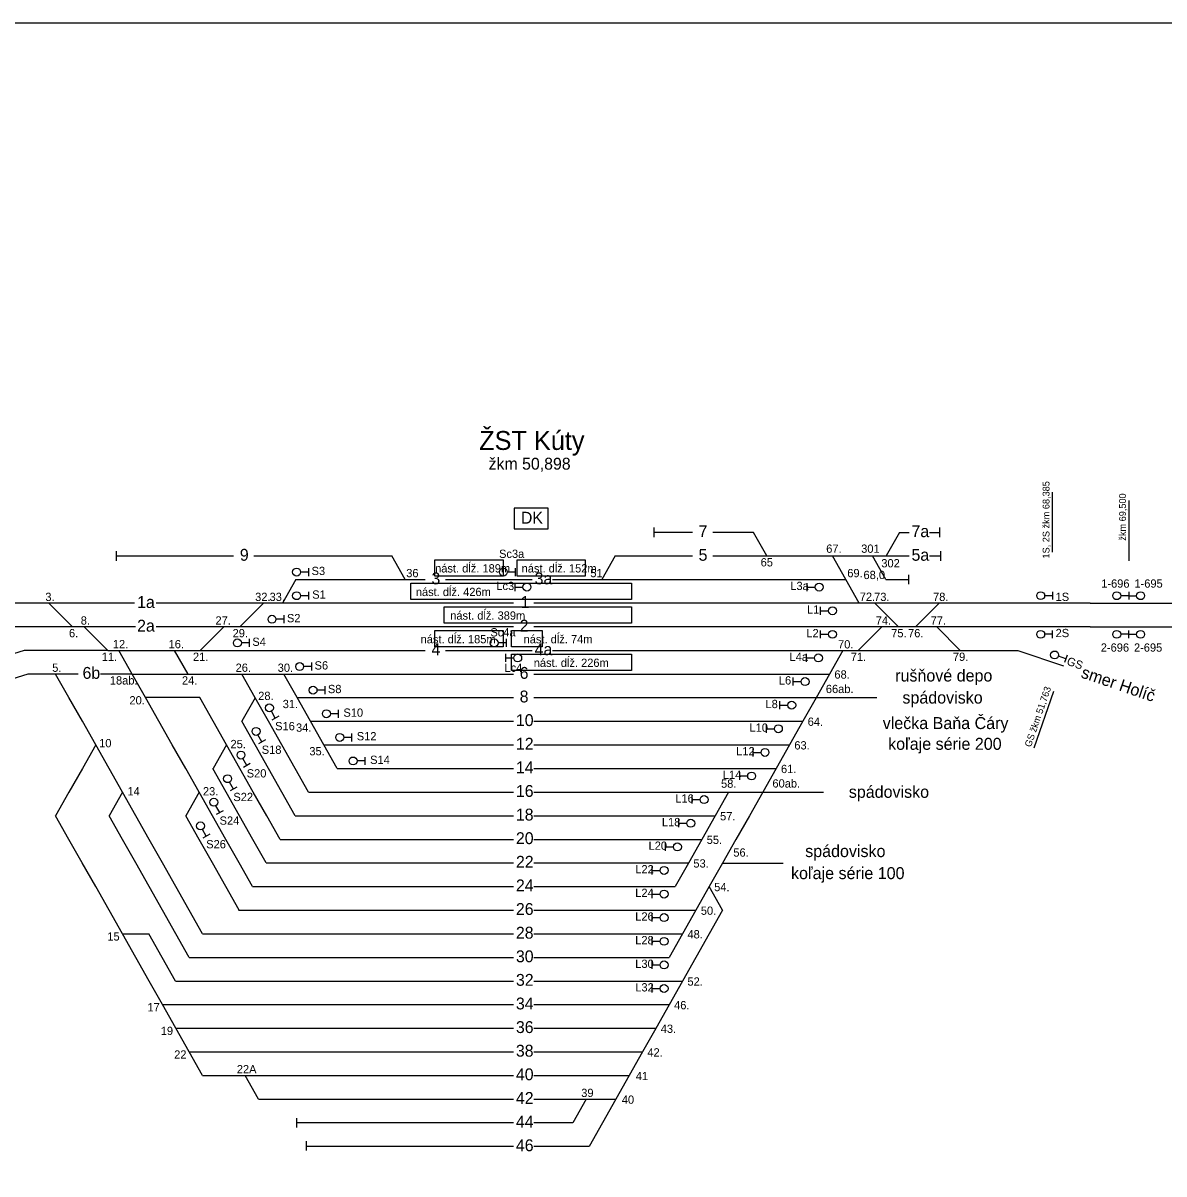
# Model space of a CAD drawing. Extents: x -119 to 851, y -238 to 59.
# Drawn here: x 501.6 to 598.1, y -38.4 to 59 of the extents above; entities that cross this region are included whole.
import ezdxf

# ---------------------------------------------------------------- set-up
doc = ezdxf.new("R2010")
doc.units = 0
for name, color, linetype in [('budova', 7, 'Continuous'), ('Level 2', 7, 'Continuous'), ('nastupistia', 7, 'Continuous'), ('netlač', 7, 'Continuous'), ('popisky navestidla', 7, 'Continuous'), ('popisky stanic a zastavok', 7, 'Continuous'), ('PU_navestidla', 7, 'Continuous'), ('PU_oznacenie navestidiel', 7, 'Continuous'), ('PU_stan_kolaje', 7, 'Continuous'), ('PU_vlecky', 7, 'Continuous'), ('schema_km1-0', 7, 'Continuous')]:
    doc.layers.add(name, color=color, linetype=linetype)

msp = doc.modelspace()

# ---------------------------------------------------------------- linework, layer by layer
at = {"layer": 'budova'}
msp.add_lwpolyline([(546.002, 17.928), (543.135, 17.928), (543.135, 16.18), (546.002, 16.18)], close=True, dxfattribs=at)
at = {"layer": 'Level 2'}
for p, q in [((554.952, 16.285), (554.952, 15.485)), ((579.115, 16.285), (579.115, 15.485)), ((509.446, 14.286), (509.446, 13.487)), ((579.194, 14.286), (579.194, 13.486)), ((576.487, 12.287), (576.487, 11.488)), ((511.009, 9.889), (496.537, 9.889)), ((523.736, 9.889), (512.835, 9.889)), ((543.056, 9.889), (523.736, 9.889)), ((553.177, 9.889), (544.779, 9.889)), ((567.83, 9.889), (553.177, 9.889)), ((591.856, 9.889), (567.83, 9.889)), ((511.071, 7.89), (496.537, 7.89)), ((543.056, 7.89), (512.817, 7.89)), ((553.177, 7.89), (544.779, 7.89)), ((566.63, 7.89), (553.177, 7.89)), ((582.828, 7.89), (566.63, 7.89)), ((591.856, 7.89), (582.828, 7.89)), ((524.714, -33.689), (524.714, -34.489)), ((525.51, -35.629), (525.51, -36.428))]:
    msp.add_line(p, q, dxfattribs=at)
at = {"layer": 'nastupistia'}
for points in [[(536.416, 13.571), (542.191, 13.571), (542.191, 12.186), (536.416, 12.186)], [(543.364, 13.571), (549.139, 13.571), (549.139, 12.186), (543.364, 12.186)], [(534.378, 11.576), (553.061, 11.576), (553.061, 10.191), (534.378, 10.191)], [(537.188, 9.577), (553.061, 9.577), (553.061, 8.192), (537.188, 8.192)], [(536.416, 7.576), (542.191, 7.576), (542.191, 6.191), (536.416, 6.191)], [(542.901, 7.576), (545.495, 7.576), (545.495, 6.191), (542.901, 6.191)], [(542.901, 5.578), (553.061, 5.578), (553.061, 4.193), (542.901, 4.193)]]:
    msp.add_lwpolyline(points, close=True, dxfattribs=at)
at = {"layer": 'netlač'}
for p, q in [((558.196, 15.885), (554.952, 15.885)), ((563.377, 15.885), (559.919, 15.885)), ((575.729, 15.885), (576.53, 15.885)), ((578.254, 15.885), (579.115, 15.885)), ((509.446, 13.887), (519.382, 13.886)), ((521.105, 13.886), (532.767, 13.886)), ((551.667, 13.887), (558.196, 13.886)), ((559.919, 13.886), (570.062, 13.886)), ((570.062, 13.886), (576.53, 13.886)), ((578.254, 13.886), (579.194, 13.886)), ((524.649, 11.888), (535.593, 11.888)), ((537.316, 11.888), (544.643, 11.888)), ((546.366, 11.888), (571.192, 11.888)), ((574.579, 11.888), (576.487, 11.888)), ((591.856, 9.889), (629.005, 9.889)), ((591.856, 7.89), (629.005, 7.89)), ((501.658, 5.891), (490.127, 2.209)), ((508.74, 5.891), (501.658, 5.891)), ((508.74, 5.891), (535.593, 5.891)), ((537.316, 5.891), (544.643, 5.891)), ((546.366, 5.891), (580.871, 5.891)), ((580.871, 5.891), (585.745, 5.891)), ((585.745, 5.891), (589.598, 4.576)), ((501.97, 3.892), (500.087, 3.291)), ((504.324, 3.892), (501.97, 3.892)), ((506.243, 3.892), (504.324, 3.892)), ((510.809, 3.892), (508.115, 3.892)), ((510.809, 3.892), (543.056, 3.892)), ((544.779, 3.892), (569.802, 3.892)), ((524.755, 1.894), (543.056, 1.894)), ((544.779, 1.894), (568.672, 1.894)), ((568.672, 1.894), (573.804, 1.894)), ((525.885, -0.105), (543.056, -0.105)), ((544.779, -0.105), (567.542, -0.105)), ((527.015, -2.103), (543.056, -2.103)), ((544.779, -2.103), (566.412, -2.103)), ((528.144, -4.102), (543.056, -4.102)), ((544.779, -4.102), (565.282, -4.102)), ((525.715, -6.101), (543.056, -6.101)), ((544.779, -6.101), (564.152, -6.101)), ((564.15, -6.103), (569.282, -6.103)), ((524.585, -8.1), (543.056, -8.1)), ((544.779, -8.1), (560.131, -8.1)), ((523.311, -10.097), (543.056, -10.097)), ((544.779, -10.097), (559.002, -10.097)), ((522.144, -12.094), (543.056, -12.094)), ((544.779, -12.094), (557.873, -12.094)), ((560.76, -12.1), (565.892, -12.1)), ((520.978, -14.094), (543.056, -14.094)), ((544.779, -14.094), (556.742, -14.094)), ((519.811, -16.091), (543.056, -16.091)), ((544.779, -16.091), (558.503, -16.091)), ((509.973, -18.093), (512.217, -18.093)), ((516.757, -18.097), (543.056, -18.097)), ((544.779, -18.097), (557.369, -18.097)), ((515.627, -20.096), (543.056, -20.096)), ((544.779, -20.096), (556.239, -20.096)), ((514.477, -22.09), (543.056, -22.09)), ((544.779, -22.09), (557.372, -22.09)), ((513.363, -24.088), (543.056, -24.088)), ((544.779, -24.088), (556.242, -24.088)), ((514.493, -26.087), (543.056, -26.087)), ((544.779, -26.087), (555.112, -26.087)), ((515.623, -28.085), (543.056, -28.085)), ((544.779, -28.085), (553.982, -28.085)), ((516.753, -30.084), (543.056, -30.084)), ((544.779, -30.084), (552.852, -30.084)), ((521.487, -32.082), (543.056, -32.082)), ((544.779, -32.082), (551.722, -32.082)), ((543.056, -34.089), (524.714, -34.089)), ((548.081, -34.089), (544.779, -34.089)), ((543.056, -36.088), (525.51, -36.088)), ((549.457, -36.088), (544.779, -36.088))]:
    msp.add_line(p, q, dxfattribs=at)
at = {"layer": 'popisky navestidla'}
for p, q in [((588.677, 14.202), (588.677, 19.293)), ((595.147, 13.488), (595.147, 18.579)), ((588.742, 2.424), (587.098, -2.394))]:
    msp.add_line(p, q, dxfattribs=at)
msp.add_lwpolyline([(-118.951, -238.008), (851.049, -238.008), (851.049, 58.992), (-118.951, 58.992)], close=True, dxfattribs=at)
at = {"layer": 'PU_navestidla'}
for p, q in [((525.724, 12.86), (525.724, 12.188)), ((543.213, 12.86), (543.213, 12.188)), ((525.724, 12.522), (525.052, 12.522)), ((543.213, 12.522), (542.541, 12.522)), ((525.724, 10.861), (525.724, 10.189)), ((543.192, 10.916), (543.192, 11.588)), ((543.192, 11.253), (543.864, 11.253)), ((567.919, 10.916), (567.919, 11.588)), ((567.919, 11.253), (568.591, 11.253)), ((588.677, 10.862), (588.677, 10.19)), ((595.114, 10.86), (595.114, 10.188)), ((595.114, 10.86), (595.114, 10.188)), ((525.724, 10.523), (525.052, 10.523)), ((588.677, 10.525), (588.005, 10.525)), ((595.114, 10.522), (594.442, 10.522)), ((595.114, 10.522), (595.786, 10.522)), ((523.639, 8.862), (523.639, 8.19)), ((569.049, 8.917), (569.049, 9.589)), ((569.049, 9.254), (569.721, 9.254)), ((523.639, 8.524), (522.967, 8.524)), ((520.712, 6.863), (520.712, 6.191)), ((542.437, 6.863), (542.437, 6.191)), ((569.049, 6.918), (569.049, 7.59)), ((569.049, 7.255), (569.721, 7.255)), ((588.677, 7.255), (588.005, 7.255)), ((588.677, 6.918), (588.677, 7.59)), ((595.114, 7.254), (594.442, 7.254)), ((595.114, 6.917), (595.114, 7.589)), ((595.114, 6.917), (595.114, 7.589)), ((595.114, 7.254), (595.786, 7.254)), ((520.712, 6.525), (520.04, 6.525)), ((542.437, 6.526), (541.765, 6.526)), ((542.411, 4.92), (542.411, 5.592)), ((542.411, 5.257), (543.083, 5.257)), ((567.856, 4.92), (567.856, 5.592)), ((567.856, 5.257), (568.528, 5.257)), ((589.804, 5.178), (589.168, 5.395)), ((589.913, 5.497), (589.696, 4.861)), ((525.98, 4.526), (525.308, 4.526)), ((525.98, 4.864), (525.98, 4.192)), ((566.726, 2.921), (566.726, 3.593)), ((566.726, 3.258), (567.398, 3.258)), ((527.11, 2.528), (526.438, 2.528)), ((527.11, 2.865), (527.11, 2.193)), ((565.596, 0.923), (565.596, 1.595)), ((565.596, 1.26), (566.268, 1.26)), ((522.907, 0.155), (522.576, 0.74)), ((523.2, 0.321), (522.615, -0.01)), ((528.24, 0.529), (527.568, 0.529)), ((528.24, 0.867), (528.24, 0.195)), ((564.466, -1.076), (564.466, -0.404)), ((564.466, -0.738), (565.138, -0.738)), ((521.777, -1.844), (521.446, -1.259)), ((522.07, -1.678), (521.485, -2.009)), ((529.37, -1.469), (528.698, -1.469)), ((529.37, -1.132), (529.37, -1.804)), ((563.336, -3.074), (563.336, -2.402)), ((563.336, -2.737), (564.008, -2.737)), ((520.502, -3.842), (520.172, -3.257)), ((520.796, -3.676), (520.211, -4.006)), ((530.5, -3.467), (529.828, -3.467)), ((530.5, -3.13), (530.5, -3.802)), ((562.206, -5.073), (562.206, -4.401)), ((562.206, -4.735), (562.878, -4.735)), ((519.372, -5.841), (519.041, -5.256)), ((519.666, -5.675), (519.081, -6.005)), ((558.185, -7.072), (558.185, -6.4)), ((558.185, -6.734), (558.857, -6.734)), ((518.206, -7.839), (517.875, -7.254)), ((518.499, -7.673), (517.914, -8.004)), ((557.055, -9.071), (557.055, -8.399)), ((557.055, -8.733), (557.727, -8.733)), ((517.075, -9.838), (516.745, -9.253)), ((517.369, -9.672), (516.784, -10.003)), ((555.925, -11.07), (555.925, -10.398)), ((555.925, -10.732), (556.597, -10.732)), ((554.798, -13.062), (554.798, -12.39)), ((554.798, -12.725), (555.47, -12.725)), ((554.798, -15.062), (554.798, -14.39)), ((554.798, -14.725), (555.47, -14.725)), ((554.798, -17.059), (554.798, -16.387)), ((554.798, -16.722), (555.47, -16.722)), ((554.798, -19.066), (554.798, -18.394)), ((554.798, -18.728), (555.47, -18.728)), ((554.798, -21.065), (554.798, -20.393)), ((554.798, -20.727), (555.47, -20.727)), ((554.798, -23.058), (554.798, -22.386)), ((554.798, -22.721), (555.47, -22.721))]:
    msp.add_line(p, q, dxfattribs=at)
for centre in [(524.716, 12.524), (542.205, 12.524), (524.716, 10.525), (544.2, 11.252), (568.927, 11.252), (587.669, 10.526), (594.106, 10.524), (596.122, 10.524), (522.631, 8.526), (570.057, 9.253), (519.704, 6.527), (541.429, 6.527), (570.057, 7.254), (587.669, 7.254), (594.106, 7.253), (596.122, 7.253), (543.419, 5.256), (568.864, 5.256), (588.85, 5.505), (524.972, 4.528), (567.734, 3.257), (526.102, 2.529), (522.412, 1.033), (566.604, 1.259), (527.232, 0.531), (521.282, -0.966), (565.474, -0.74), (528.362, -1.468), (520.008, -2.964), (564.344, -2.738), (529.492, -3.466), (518.877, -4.963), (563.214, -4.737), (517.711, -6.961), (559.193, -6.736), (516.581, -8.96), (558.063, -8.735), (556.933, -10.734), (555.806, -12.726), (555.806, -14.726), (555.806, -16.723), (555.806, -18.73), (555.806, -20.729), (555.806, -22.722)]:
    msp.add_circle(centre, 0.336, dxfattribs=at)
at = {"layer": 'PU_stan_kolaje'}
for points in [[(564.507, 13.887), (563.377, 15.885)], [(575.729, 15.885), (574.598, 13.886)], [(533.897, 11.888), (532.767, 13.886)], [(551.667, 13.887), (550.537, 11.888)], [(571.192, 11.888), (570.062, 13.886)], [(574.579, 11.888), (573.45, 13.886)], [(524.649, 11.888), (523.518, 9.889)], [(572.322, 9.889), (571.192, 11.887)], [(505.743, 7.89), (503.744, 9.889)], [(519.905, 7.89), (521.904, 9.889)], [(575.649, 7.89), (573.65, 9.889)], [(577.076, 7.89), (579.075, 9.889)], [(508.74, 5.891), (506.741, 7.89)], [(516.549, 5.891), (518.548, 7.89)], [(572.23, 5.891), (574.229, 7.89)], [(580.871, 5.891), (578.872, 7.89)], [(510.809, 3.892), (509.679, 5.891)], [(515.525, 3.892), (514.395, 5.891)], [(570.932, 5.891), (569.802, 3.892)], [(505.454, 1.894), (504.324, 3.892)], [(511.938, 1.894), (510.809, 3.892)], [(521.196, 1.893), (520.066, 3.892)], [(524.755, 1.894), (523.625, 3.892)], [(569.802, 3.892), (568.671, 1.893)], [(506.584, -0.105), (505.454, 1.894)], [(513.068, -0.105), (511.938, 1.894)], [(516.531, 1.894), (511.938, 1.894)], [(517.661, -0.105), (516.531, 1.894)], [(521.196, 1.893), (520.065, -0.106)], [(522.325, -0.105), (521.196, 1.893)], [(525.885, -0.105), (524.755, 1.894)], [(568.671, 1.893), (567.541, -0.106)], [(507.714, -2.103), (506.584, -0.105)], [(514.198, -2.103), (513.068, -0.105)], [(518.791, -2.103), (517.661, -0.105)], [(521.195, -2.104), (520.065, -0.106)], [(523.455, -2.104), (522.325, -0.105)], [(527.015, -2.103), (525.885, -0.105)], [(567.541, -0.106), (566.411, -2.105)], [(507.714, -2.103), (506.584, -4.102)], [(508.844, -4.102), (507.714, -2.103)], [(515.328, -4.102), (514.198, -2.103)], [(518.791, -2.103), (517.661, -4.102)], [(519.921, -4.102), (518.791, -2.103)], [(522.325, -4.103), (521.195, -2.104)], [(524.585, -4.102), (523.455, -2.104)], [(528.144, -4.102), (527.015, -2.103)], [(566.411, -2.105), (565.281, -4.104)], [(506.584, -4.102), (505.454, -6.101)], [(509.974, -6.1), (508.844, -4.102)], [(516.458, -6.1), (515.328, -4.102)], [(518.755, -6.1), (517.625, -4.102)], [(521.051, -6.1), (519.921, -4.102)], [(523.455, -6.101), (522.325, -4.103)], [(525.715, -6.101), (524.585, -4.102)], [(565.281, -4.104), (564.15, -6.103)], [(505.454, -6.101), (504.323, -8.1)], [(509.974, -6.1), (508.844, -8.099)], [(511.104, -8.099), (509.974, -6.1)], [(516.458, -6.1), (515.328, -8.099)], [(517.588, -8.099), (516.458, -6.1)], [(519.885, -8.099), (518.755, -6.1)], [(522.181, -8.099), (521.051, -6.1)], [(524.585, -8.1), (523.455, -6.101)], [(561.26, -6.103), (560.13, -8.102)], [(564.15, -6.103), (563.02, -8.102)], [(505.453, -10.099), (504.323, -8.1)], [(509.974, -10.098), (508.844, -8.099)], [(512.234, -10.097), (511.104, -8.099)], [(516.458, -10.098), (515.328, -8.099)], [(518.718, -10.097), (517.588, -8.099)], [(521.015, -10.097), (519.885, -8.099)], [(523.311, -10.097), (522.181, -8.099)], [(560.13, -8.102), (558.999, -10.101)], [(563.02, -8.102), (561.89, -10.101)], [(506.583, -12.097), (505.453, -10.099)], [(511.104, -12.096), (509.974, -10.098)], [(513.364, -12.096), (512.234, -10.097)], [(517.588, -12.096), (516.458, -10.098)], [(519.848, -12.096), (518.718, -10.097)], [(522.145, -12.096), (521.015, -10.097)], [(558.999, -10.101), (557.869, -12.1)], [(561.89, -10.101), (560.76, -12.1)], [(507.713, -14.096), (506.583, -12.097)], [(512.234, -14.095), (511.104, -12.096)], [(514.494, -14.094), (513.364, -12.096)], [(518.718, -14.095), (517.588, -12.096)], [(520.978, -14.094), (519.848, -12.096)], [(557.869, -12.1), (556.739, -14.099)], [(560.76, -12.1), (559.629, -14.099)], [(508.843, -16.094), (507.713, -14.096)], [(513.364, -16.093), (512.234, -14.095)], [(515.624, -16.093), (514.494, -14.094)], [(519.848, -16.093), (518.718, -14.095)], [(559.629, -14.099), (558.499, -16.098)], [(560.759, -16.098), (559.629, -14.099)], [(509.973, -18.093), (508.843, -16.094)], [(514.494, -18.092), (513.364, -16.093)], [(516.754, -18.091), (515.624, -16.093)], [(558.499, -16.098), (557.369, -18.097)], [(560.759, -16.098), (559.629, -18.097)], [(511.103, -20.091), (509.973, -18.093)], [(513.347, -20.091), (512.217, -18.093)], [(515.624, -20.09), (514.494, -18.092)], [(557.369, -18.097), (556.239, -20.096)], [(559.629, -18.097), (558.499, -20.096)], [(512.233, -22.09), (511.103, -20.091)], [(514.477, -22.09), (513.347, -20.091)], [(558.499, -20.096), (557.369, -22.095)], [(513.363, -24.088), (512.233, -22.09)], [(557.369, -22.095), (556.238, -24.094)], [(514.493, -26.087), (513.363, -24.088)], [(556.238, -24.094), (555.108, -26.093)], [(515.623, -28.085), (514.493, -26.087)], [(555.108, -26.093), (553.978, -28.092)], [(516.753, -30.084), (515.623, -28.085)], [(553.978, -28.092), (552.848, -30.091)], [(521.487, -32.082), (520.357, -30.084)], [(552.848, -30.091), (551.717, -32.09)], [(549.211, -32.09), (548.081, -34.089)], [(551.717, -32.09), (550.587, -34.089)], [(550.587, -34.089), (549.457, -36.088)]]:
    msp.add_lwpolyline(points, dxfattribs=at)

# ---------------------------------------------------------------- texts
at = {"layer": 'budova'}
msp.add_text('DK', height=1.0044, dxfattribs=at).set_placement((543.69, 16.619))
at = {"layer": 'nastupistia'}
for s, p in [('nást. dĺž. 189m', (536.431, 12.489)), ('nást. dĺž. 152m', (543.75, 12.489)), ('nást. dĺž. 426m', (534.799, 10.493)), ('nást. dĺž. 389m', (537.711, 8.494)), ('nást. dĺž. 185m', (535.204, 6.494)), ('nást. dĺž. 74m', (543.919, 6.494)), ('nást. dĺž. 226m', (544.777, 4.496))]:
    msp.add_text(s, height=0.7, dxfattribs=at).set_placement(p)
at = {"layer": 'popisky navestidla'}
for s, height, rotation, p in [('1S, 2S žkm 68,385', 0.57931, 90, (588.414, 13.671)), ('žkm 69,500', 0.5793, 90, (594.884, 15.18)), ('GS žkm 51,763', 0.57931, 71.15515, (586.839, -2.338))]:
    msp.add_text(s, height=height, rotation=rotation, dxfattribs=at).set_placement(p)
at = {"layer": 'popisky stanic a zastavok'}
for s, height, p in [('ŽST Kúty', 1.6, (540.157, 22.86)), ('žkm 50,898', 1.0044, (540.956, 21.191))]:
    msp.add_text(s, height=height, dxfattribs=at).set_placement(p)
at = {"layer": 'PU_oznacenie navestidiel'}
for s, p in [('67.', (569.523, 14.155)), ('301', (572.483, 14.155)), ('Sc3a', (541.842, 13.719)), ('65', (563.974, 13.001)), ('S3', (525.978, 12.271)), ('36', (533.989, 12.085)), ('51', (549.561, 12.085)), ('69.', (571.307, 12.085)), ('302', (574.186, 12.921)), ('Lc3', (541.613, 11.002)), ('L3a', (566.485, 11.002)), ('1-696', (592.792, 11.203)), ('1-695', (595.6, 11.203)), ('3.', (503.455, 10.075)), ('32.', (521.205, 10.075)), ('33.', (522.425, 10.075)), ('S1', (526.033, 10.272)), ('72.', (572.361, 10.086)), ('73.', (573.575, 10.075)), ('78.', (578.563, 10.075)), ('1S', (588.932, 10.076)), ('8.', (506.452, 8.076)), ('27.', (517.848, 8.076)), ('S2', (523.895, 8.273)), ('L1', (567.895, 9.003)), ('74.', (573.717, 8.076)), ('77.', (578.36, 8.076)), ('6.', (505.454, 7.004)), ('29.', (519.299, 7.004)), ('S4', (520.967, 6.274)), ('Sc4a', (541.109, 7.076)), ('L2', (567.842, 7.004)), ('75.', (575.022, 7.004)), ('76.', (576.449, 7.004)), ('2S', (588.932, 7.015)), ('12.', (509.167, 6.077)), ('16.', (513.883, 6.077)), ('70.', (570.523, 6.059)), ('2-696', (592.754, 5.786)), ('2-695', (595.561, 5.786)), ('11.', (508.228, 5.005)), ('21.', (515.943, 5.005)), ('S6', (526.234, 4.275)), ('L4a', (566.422, 5.006)), ('71.', (571.603, 5.005)), ('79.', (580.244, 5.005)), ('5.', (504.035, 4.078)), ('26.', (519.554, 4.078)), ('30.', (523.113, 4.078)), ('Lc4', (542.305, 4.079)), ('68.', (570.216, 3.506)), ('18ab.', (508.912, 3.006)), ('24.', (515.013, 3.006)), ('S8', (527.363, 2.276)), ('L6', (565.516, 3.007)), ('66ab.', (569.493, 2.281)), ('20.', (510.57, 1.322)), ('28.', (521.465, 1.696)), ('31.', (523.534, 1.008)), ('S10', (528.674, 0.278)), ('L8', (564.386, 1.009)), ('64.', (567.956, -0.492)), ('S16', (522.896, -0.864)), ('34.', (524.664, -0.991)), ('L10', (563.034, -0.99)), ('10', (508.006, -2.308)), ('25.', (519.12, -2.383)), ('S12', (529.806, -1.72)), ('63.', (566.825, -2.491)), ('S18', (521.764, -2.863)), ('35.', (525.794, -2.989)), ('L12', (561.906, -2.988)), ('S14', (530.934, -3.719)), ('61.', (565.695, -4.49)), ('S20', (520.492, -4.861)), ('L14', (560.774, -4.987)), ('14', (510.4, -6.38)), ('23.', (516.787, -6.38)), ('58.', (560.625, -5.732)), ('60ab.', (564.972, -5.715)), ('S22', (519.363, -6.86)), ('L16', (556.753, -6.986)), ('57.', (560.544, -8.488)), ('S24', (518.195, -8.858)), ('L18', (555.622, -8.985)), ('S26', (517.064, -10.857)), ('L20', (554.493, -10.984)), ('55.', (559.414, -10.487)), ('56.', (561.665, -11.561)), ('L22', (553.368, -12.976)), ('53.', (558.284, -12.486)), ('L24', (553.366, -14.976)), ('54.', (560.044, -14.485)), ('L26', (553.366, -16.973)), ('50.', (558.914, -16.484)), ('15', (508.699, -18.664)), ('L28', (553.365, -18.98)), ('48.', (557.783, -18.483)), ('L30', (553.366, -20.979)), ('L32', (553.368, -22.972)), ('52.', (557.783, -22.481)), ('17', (512.091, -24.66)), ('46.', (556.653, -24.48)), ('19', (513.22, -26.658)), ('43.', (555.523, -26.479)), ('22', (514.353, -28.657)), ('42.', (554.392, -28.478)), ('22A', (519.654, -29.898)), ('41', (553.413, -30.477)), ('39', (548.794, -31.904)), ('40', (552.229, -32.476))]:
    msp.add_text(s, height=0.7, dxfattribs=at).set_placement(p)
msp.add_text('GS', height=0.7, rotation=341.15515, dxfattribs=at).set_placement((589.817, 4.699))
at = {"layer": 'PU_stan_kolaje'}
for s, height, p in [('7', 1.004, (558.729, 15.48)), ('7a', 1.0044, (576.741, 15.48)), ('9', 1.004, (519.913, 13.482)), ('5', 1.004, (558.725, 13.481)), ('5a', 1.0044, (576.741, 13.481)), ('3', 1.004, (536.126, 11.483)), ('3a', 1.0044, (544.854, 11.483)), ('1a', 1.0044, (511.22, 9.484)), ('1', 1.004, (543.668, 9.484)), ('2a', 1.0044, (511.22, 7.485)), ('2', 1.004, (543.592, 7.485)), ('4', 1.004, (536.126, 5.486)), ('4a', 1.0044, (544.854, 5.486)), ('6b', 1.0044, (506.601, 3.487)), ('6', 1.004, (543.588, 3.487)), ('8', 1.004, (543.587, 1.489)), ('10', 1.0044, (543.269, -0.51)), ('12', 1.0044, (543.272, -2.508)), ('14', 1.0044, (543.269, -4.507)), ('16', 1.0044, (543.269, -6.506)), ('18', 1.0044, (543.267, -8.505)), ('20', 1.0044, (543.269, -10.502)), ('22', 1.0044, (543.272, -12.499)), ('24', 1.0044, (543.269, -14.499)), ('26', 1.0044, (543.269, -16.496)), ('28', 1.0044, (543.267, -18.502)), ('30', 1.0044, (543.269, -20.501)), ('32', 1.0044, (543.272, -22.494)), ('34', 1.0044, (543.269, -24.493)), ('36', 1.0044, (543.269, -26.491)), ('38', 1.0044, (543.267, -28.49)), ('40', 1.0044, (543.269, -30.488)), ('42', 1.0044, (543.272, -32.487)), ('44', 1.0044, (543.269, -34.494)), ('46', 1.0044, (543.269, -36.493))]:
    msp.add_text(s, height=height, dxfattribs=at).set_placement(p)
at = {"layer": 'PU_vlecky'}
for s, p in [('rušňové depo', (575.356, 3.261)), ('spádovisko', (575.971, 1.395)), ('vlečka Baňa Čáry', (574.306, -0.765)), ('koľaje série 200', (574.763, -2.521)), ('spádovisko', (571.435, -6.584)), ('spádovisko', (567.745, -11.599)), ('koľaje série 100', (566.547, -13.465))]:
    msp.add_text(s, height=1.015, dxfattribs=at).set_placement(p)
msp.add_text('smer Holíč', height=1.015, rotation=341.15515, dxfattribs=at).set_placement((591.014, 3.619))
at = {"layer": 'schema_km1-0'}
msp.add_text('68,0', height=0.7, dxfattribs=at).set_placement((572.679, 11.93))

doc.saveas('drawing.dxf')
